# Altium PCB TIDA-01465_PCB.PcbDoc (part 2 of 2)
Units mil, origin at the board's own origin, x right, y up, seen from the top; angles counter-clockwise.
Board outline 2770 x 2010 mil, 4 copper layers (Top Layer, MidLayer1, MidLayer2, Bottom Layer), stack 61.2 mil thick; 110 components, 69 nets, 347 pads, 90 vias.
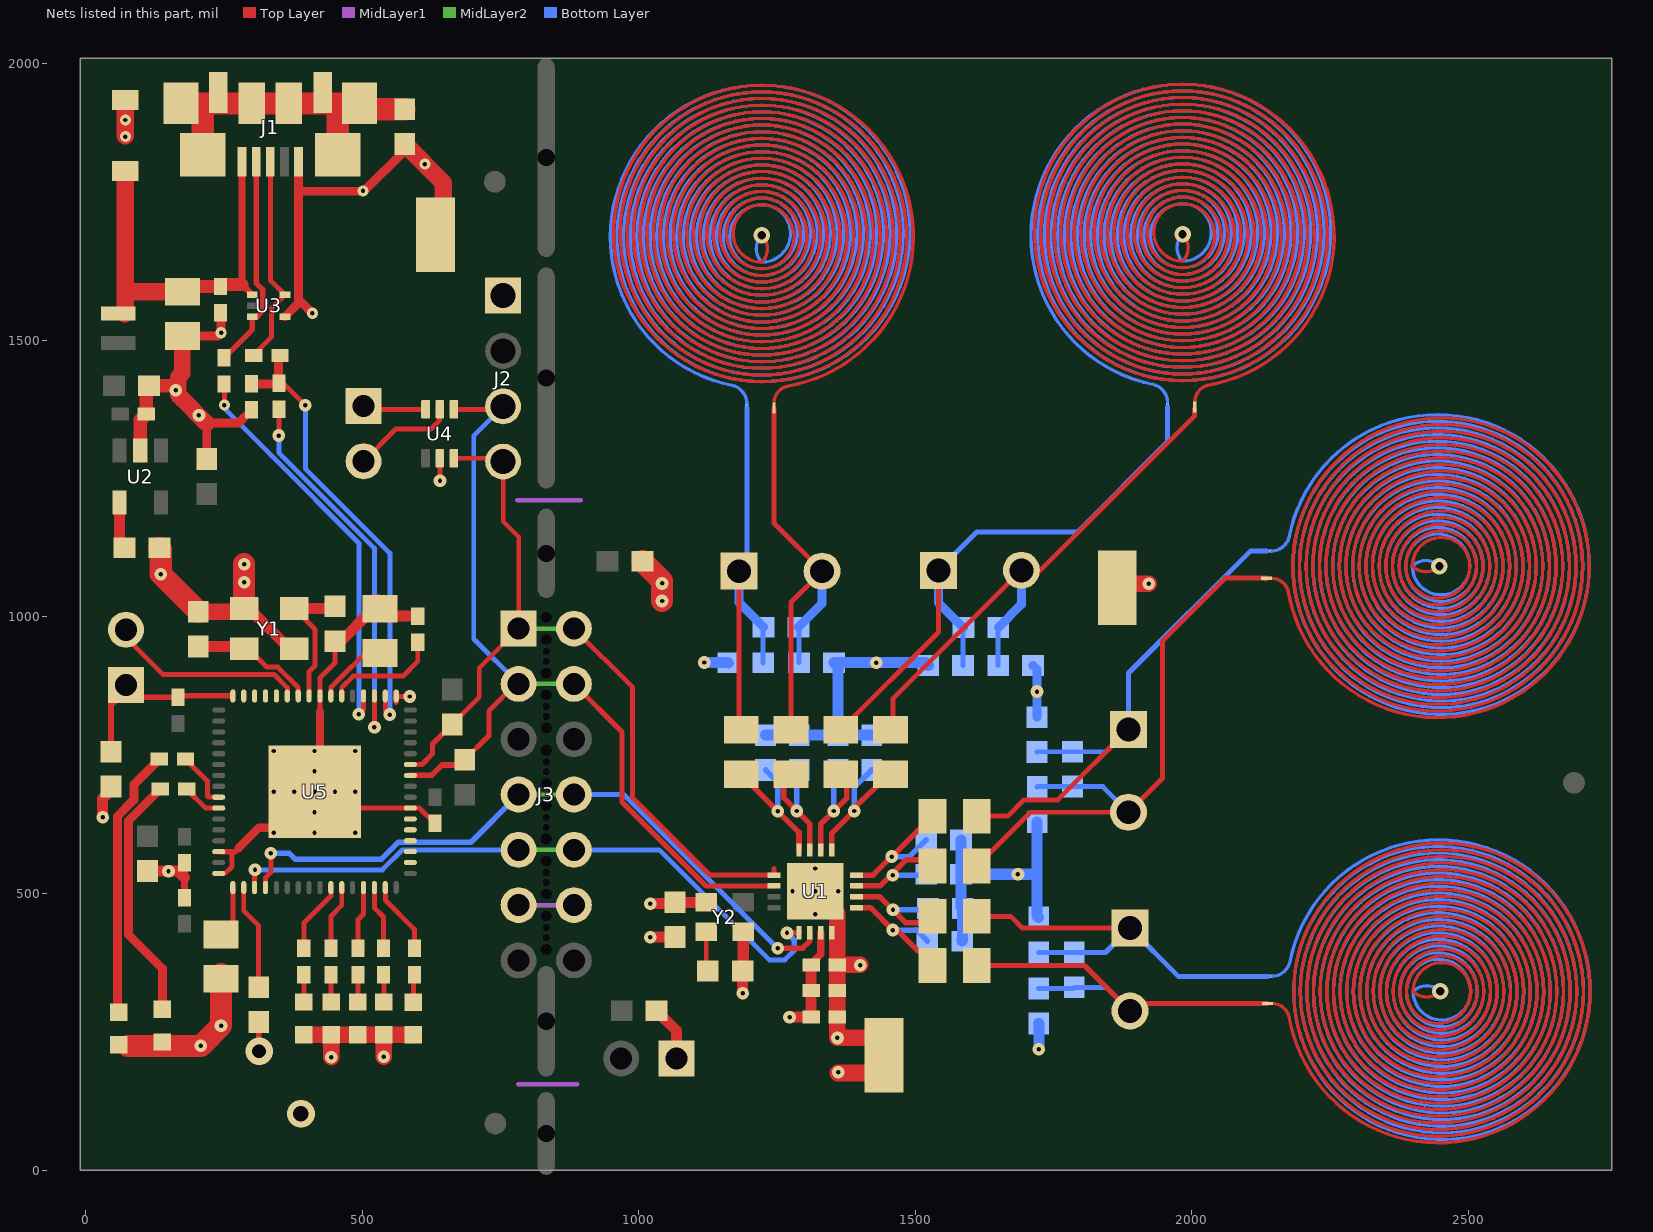
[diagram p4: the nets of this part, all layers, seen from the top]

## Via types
v1: diameter 23, hole 8, Top Layer to Bottom Layer, tented both sides, 58 vias
v2: diameter 19.68, hole 7.87, Top Layer to Bottom Layer, 18 vias
v3: diameter 20, hole 8, Top Layer to Bottom Layer, tented both sides, 7 vias
v4: diameter 30, hole 15, Top Layer to Bottom Layer, tented both sides, 4 vias
v5: diameter 50, hole 25, Top Layer to Bottom Layer, 2 vias
v6: diameter 50, hole 28, Top Layer to Bottom Layer, 1 vias

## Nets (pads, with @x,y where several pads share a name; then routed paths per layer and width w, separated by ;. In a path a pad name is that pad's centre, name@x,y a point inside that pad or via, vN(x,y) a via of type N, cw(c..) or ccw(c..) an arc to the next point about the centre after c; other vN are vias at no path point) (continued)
GND: C1.2 C2.2 C3.2 C4.2 C5.2 C6.2 C8.2 C9.2 C11.1 C12.1 C13.1 C14.1 C16.2 C18.2 C19.1 C20.1 C21.1 C23.2 C25.2 C26.2 C27.1 C28.2 C29.2 C30.2 C31.2 C32.2 C33.2 C34.2 C35.2 C36.2 C37.1 C38.2 C39.1 C41.2 C42.1 C44.2 D1.2 D2.2 D3.2 D4.2 D5.2 D6.2 D7.2 D8.1 GND1.1 GND2.1 GND3.1 J1.5 J2.1 J3.11 J3.12 R7.1 R15.1 R16.1 U1.8 U1.17 U2.2 U3.4 U4.2 U5.14 U5.16 U5.39 U5.49 U5.56 U5.65 Y1.2 Y1.4 Y2.2 | length 6001.8
  Top Layer w9: U5.16@240.77,536.36 241.05,536.64 252.81,536.64 265.08,548.91 265.08,570.23 ; U5.65@331,619 396,684 v2(414,684) ; v2(340.18,684) 354,684 U5.65@420.91,750.91 ; 423.85,829 U5.56@423.85,857.23 423.85,889.99 450.96,917.11 C14.1@450.96,945.31 ; U5.65@443.53,654.47 U5.39@587.23,654.47 603.82,654.47 C33.2@631.54,626.75 ; U5.49@561.67,845.47 U5.49@561.67,857.23 562.71,856.19 v1(586.36,856.19) ; U4.2@640.39,1287.05 640.02,1286.67 640.83,1285.87 v1(640.83,1246.36) ; R16.1@1188.14,359.81 R16.1@1189.18,360.85
  Top Layer w10: U5.14@240.77,575.73 270.59,575.73 276.93,582.07
  Top Layer w12: C32.2@178.89,492.62 C32.2@179,492.62 179,529 C30.2@179,555.38
  Top Layer w15: 276.93,582.07 313.86,619 U5.65@331,619 ; U5.65@423.85,693.84 423.85,829
  Top Layer w16: C31.2@112,535.18 C31.2@112,540.5 ; 175,1394 175,1394.12 ; C8.2@175,1508 239,1508 v3(245,1514) C9.2@245,1549.38 ; 218,1351 276.62,1351 R15.1@300,1374.38 ; C3.2@219,1285.5 219,1350 ; U3.4@360.53,1543.32 385.18,1567.97 ; J1.5@385.18,1823.22 385.18,1769.73 ; v3(410.01,1549.25) 391.29,1567.97 385.18,1567.97 ; R7.1@577,1855.23 577,1843.43 503.29,1769.73 385.18,1769.73 ; 385.18,1567.97 385.18,1769.73
  Top Layer w20: v1(31,638) 31,671.4 30.7,671.7 C27.1@46,687 ; C31.2@112,540.5 167.5,540.5 179,529 ; Y1.2@286.72,1015.42 295.58,1015.42 368.42,942.58 Y1.4@377.28,942.58 ; C14.1@450.96,945.31 528.74,1023.09 C26.2@528.74,1031.81 ; C26.2@541.58,1001.55 C29.2@603.3,1001.55 ; v1(1020.94,421.02) 1065.57,421.02 C5.2@1065.83,421.28 ; R16.1@1188.14,359.81 1188.25,359.71 v1(1188.25,319.59) ; R16.1@1189.18,360.85 Y2.2@1189.18,430.63
  Top Layer w25: U2.2@99,1301.24 99,1356.21 C2.2@109.61,1366.82 109.61,1413.11 C1.2@114.5,1418 151.12,1418
  Top Layer w30: v1@167.38,1410 167.38,1401.74 175,1394.12 ; v1@167.38,1418 167.38,1433.39 175,1441.01 C8.2@175,1508 ; 175,1394 218,1351 219,1350 ; C13.1@204,1009.5 280.8,1009.5 Y1.2@286.72,1015.42 ; D4.2@394.55,244.76 D5.2@444.16,244.76 ; v1(444.16,203.92) D5.2@444.16,244.76 ; v1(539.4,204.69) D7.2@539.4,244.76 ; D8.1@593,243.64 591.87,244.76 D7.2@539.4,244.76 ; v2(1319.55,503.84) 1359.17,464.22 C6.2@1359.17,370.84 ; v1@1360.49,175.4 GND3.1@1444.15,175.4 ; v1@1400.28,370.84 C6.2@1359.17,370.84 ; GND3.1@1443.64,239.27 1443.21,238.84 v1(1359.55,238.84) 1359.17,239.22 C25.2@1359.17,276.84 C34.2@1359.17,324.84 C6.2@1359.17,370.84 ; GND1.1@1865.41,1053.14 1872.45,1060.19 v1(1922.53,1060.19) ; D5.2@444.16,244.76 D6.2@492.53,244.76 D7.2@539.4,244.76
  Top Layer w32: v3@72,1870.74 D1.2@72,1935.2 ; R7.1@577,1855.23 647,1785.23 GND2.1@647,1703.73
  Top Layer w40: 77,224.47 v1(208.47,224.47) v1(245,261) C28.2@245,354.5 ; C4.2@133.5,1125 135.99,1122.5 v1(135.99,1077.5) C13.1@204,1009.5 ; Y1.2@286.72,1015.42 v1(286.72,1095.28)
  MidLayer1 w8: 780.45,1210.95 895.45,1210.95 ; 782,155 889,155 ; J3.11@793,479 J3.12@883,479 J3.12@893,479
  MidLayer2 w8: J3.11@773,479 J3.11@783,479 J3.12@883,479
  Bottom Layer w16: C36.2@1713.19,912.33 1720.36,905.16 C42.1@1720.36,818.85
  Bottom Layer w20: v1(1118.75,917.78) 1161.66,917.78 C12.1@1162.25,917.19 ; C11.1@1229.55,786.34 C16.2@1290.55,786.34 C19.1@1360.55,786.34 ; C35.2@1421.55,786.34 C19.1@1360.55,786.34 ; C21.1@1523.72,912.33 1518.55,917.5 C18.2@1353.08,917.53 1360.55,910.07 C19.1@1360.55,786.34 ; C20.1@1583.04,596.84 C23.2@1583.04,534.84 ; C38.2@1585.04,413.84 1586.04,414.84 C37.1@1586.04,472.84 1583.04,475.84 C23.2@1583.04,534.84 ; 1720.17,534.84 C23.2@1583.04,534.84 ; C44.2@1720.61,629.39 1720.61,459.14 C39.1@1723.36,456.4 ; C41.2@1723.36,265.2 1723.7,264.85 v1(1723.7,218.41)
  other v1: 1360.99,176.57 1400.93,370.19 1685.9,534.76 150,540.5 1720.45,865.18 1429.67,917.4 286.72,1063 205,1365 163,1410
  other v2: 1319.55,462.5 1278.21,503.84 1360.89,503.84 1319.55,545.18 340.18,610.18 414,610.18 487.82,610.18 414,647.09 377.09,684 450.91,684 487.82,684 414,720.91 340.18,757.82 414,757.82 487.82,757.82
  other v3: 501.61,1770.4 613.5,1818.73 72,1868.73 72,1898.73
  other v6: 389.44,101.69
IN0A: C38.1 R33.1 U1.9 | length 226.6
  Top Layer w10: U1.9@1389.35,474.31 1419.07,474.31 v1(1459.55,433.84) 1467.55,433.84 1504.43,396.96 ; R33.1@1523.55,369.84 R33.1@1531.55,369.84
  Bottom Layer w10: v1(1459.55,433.84) 1500.41,433.84 1501.23,434.66 C38.1@1522.05,413.84
IN0B: C37.2 R23.1 U1.10 | length 209.8
  Top Layer w10: U1.10@1389.35,494 1436.39,494 v1(1459.97,470.42) 1483.55,446.84 R23.1@1515.55,446.84
  Bottom Layer w10: v1(1459.97,470.42) 1520.63,470.42 C37.2@1523.05,472.84
IN1A: C23.1 R20.1 U1.11 | length 205.1
  Top Layer w10: U1.11@1389.35,513.68 1436.39,513.68 1483.55,560.84 R20.1@1513.55,560.84
  Bottom Layer w10: v1(1459.55,532.84) 1518.05,532.84 C23.1@1520.05,534.84
IN1B: C20.2 R19.1 U1.12 | length 261.2
  Top Layer w10: U1.12@1389.35,533.37 1409.16,533.37 1424.07,533.37 v1(1457.55,566.84) 1458.55,566.84 R19.1@1531.55,639.84
  Bottom Layer w10: v1(1457.55,566.84) 1490.05,566.84 C20.2@1520.05,596.84
IN2A: C35.1 R28.1 U1.13 | length 269.3
  Top Layer w10: U1.13@1349.07,578.64 1349.07,608.6 v1(1389.74,649.26) 1389.74,654.97 1450.48,712.68 1455.46,712.56 R28.1@1455.55,712.55
  Bottom Layer w10: v1(1389.74,649.26) 1389.74,691.54 C35.1@1421.55,723.34
IN2B: C19.2 R27.1 U1.14 | length 223
  Top Layer w10: U1.14@1329.39,578.64 1329.39,625.68 v1(1352.97,649.26) 1376.55,672.84 R27.1@1376.55,704.84
  Bottom Layer w10: v1(1352.97,649.26) 1352.97,715.77 C19.2@1360.55,723.34
IN3A: C16.1 R26.1 U1.15 | length 219.6
  Top Layer w10: R26.1@1262.55,702.84 1262.55,672.84 1309.7,625.68 U1.15@1309.7,578.64
  Bottom Layer w10: v1(1286.13,649.26) 1286.13,718.92 C16.1@1290.55,723.34
IN3B: C11.2 R24.1 U1.16 | length 264.1
  Top Layer w10: R24.1@1185.55,715.84 1185.55,714.84 v1(1251.55,648.84) 1290.02,610.37 U1.16@1290.02,578.64
  Bottom Layer w10: C11.2@1229.55,723.34 1251.55,701.34 v1(1251.55,648.84)
INTB: J3.9 J3.10 U1.5 U5.19 | length 1154.1
  Top Layer w9: U5.19@305.71,510.77 v1@305.71,542.13
  Top Layer w10: v1@1273.13,429.04 U1.5@1290.02,429.04
  MidLayer2 w8: J3.9@783,579 J3.10@873,579
  Bottom Layer w9: v1(306.32,542.75) 536.73,542.75 572.98,579 ; 573.95,579 J3.9@783,579 ; J3.10@883,579 1037.28,579 1236.29,379.98 1264.39,379.98 1281.45,397.05
  Bottom Layer w10: v1(1268.3,428.77) 1281.45,415.62 1281.45,397.05
JTAG_RST: C27.2 J9.1 R29.2 U5.64 | length 404.6
  Top Layer w10: C27.2@46,756.5 46,840 ; U5.64@266.33,857.23 164.39,857.23 R29.2@167,854.62 J9.1@95.38,854.62 ; 46,840 71,865 81.38,854.62 J9.1@95.38,854.62 ; 46,840 46,850 J9.1@73,877 J9.1@95.38,854.62
JTAG_TCK: U5.63
JTAG_TDI: U5.61
JTAG_TDO: U5.60
JTAG_TEST: J9.2 U5.59 | length 352.9
  Top Layer w9: J9.2@67,969 139.66,896.34 340.75,896.34 364.78,872.32 U5.59@364.78,857.23
JTAG_TMS: U5.62
MSP_DM: R9.2 U5.52 | length 735.7
  Top Layer w9: R9.2@249.62,1421 R9.2@250,1421.38 250.84,1420.54 v3(250.84,1383.04) ; v1(494.07,824.02) 502.61,832.55 U5.52@502.61,857.23
  Bottom Layer w9: v3(250.84,1383.04) 250.84,1377.16 336.46,1291.54 336.46,1291.39 494.07,1133.78 v1(494.07,824.02)
MSP_DP: R6.1 R8.2 R15.2 U5.50 | length 821.2
  Top Layer w9: R6.1@350,1422.62 357.71,1422.62 v1(397.42,1382.92) ; U5.50@541.98,857.23 541.98,831.75 v1(550.14,823.6)
  Top Layer w16: R15.2@300,1421.62 349,1421.62 R8.2@349,1470.38
  Bottom Layer w9: v1(397.42,1382.92) 397.42,1268.27 550.14,1115.54 v1(550.14,823.6)
MSP_PUR: R6.2 U5.51 | length 702.8
  Top Layer w9: v1@350,1328.58 R6.2@350,1375.38 ; v1(522.3,800.45) U5.51@522.3,857.23
  Bottom Layer w9: v1(349.46,1328.05) 349.46,1297.17 522.3,1124.34 v1(522.3,800.45)
MSPACLK: R17.2 | length 53.1
  Top Layer w10: R17.2@313,267.5 313,230 313.87,229.13 v5(313.87,214.74)
NetC4_1: C4.1 U2.4 | length 85.4
  Top Layer w20: U2.4@61.6,1206.76 61.6,1133.91 C4.1@70.5,1125
NetC7_1: C7.1 C18.1 J7.2 L3.1 R26.2 | length 825
  Top Layer w9: L3.1@1244.67,1377.96 1244.67,1169.91 J7.2@1331.83,1082.75 1275.55,1026.46 R26.2@1275.55,795.84
  Bottom Layer w9: C7.1@1288.98,981.73 1290.09,980.62 C18.1@1290.09,917.53
  Bottom Layer w16: C7.1@1288.98,981.73 1331.83,1024.58 J7.2@1331.83,1082.75
NetC7_2: C7.2 C12.2 J7.1 L3.2 R24.2 | length 780.2
  Top Layer w9: R24.2@1181.83,799.55 J7.1@1181.83,1082.75
  Top Layer w16: R24.2@1181.83,799.55 R24.2@1185.55,795.84
  Bottom Layer w9: J7.1@1181.83,1082.75 J7.1@1181.83,1108.81 ; J7.1@1195.61,1096.52 1195.61,1122.58 L3.2@1195.61,1378.04 ; C12.2@1225.24,917.19 1225.24,980.98 C7.2@1225.99,981.73
  Bottom Layer w16: J7.1@1181.83,1082.75 1181.83,1025.89 C7.2@1225.99,981.73
  other v4: 1222.84,1690.53
NetC10_1: C10.1 C36.1 J6.2 L2.1 R28.2 | length 1017.5
  Top Layer w9: R28.2@1455.55,795.84 1459.79,800.08 1459.79,852.07 J6.2@1692.14,1084.42 1726.24,1084.42 2005.47,1363.64 L2.1@2005.47,1376.15
  Bottom Layer w9: C36.1@1650.2,912.33 1650.2,980.82 C10.1@1650.3,980.91
  Bottom Layer w16: C10.1@1650.3,980.91 1692.14,1022.76 J6.2@1692.14,1084.42
NetC10_2: C10.2 C21.2 J6.1 L2.2 R27.2 | length 1126.6
  Top Layer w9: R27.2@1365.55,795.84 1542.14,972.44 J6.1@1542.14,1084.42
  Bottom Layer w9: J6.1@1542.14,1084.42 1611.5,1153.78 1793.85,1153.78 1956.4,1316.34 L2.2@1956.4,1379.85 ; C21.2@1586.71,912.33 1586.71,980.31 C10.2@1587.3,980.91
  Bottom Layer w16: J6.1@1542.14,1084.42 1542.14,1026.07 C10.2@1587.3,980.91
  other v4: 1983.64,1692.34
NetC13_2: C13.2 U5.58 Y1.3 | length 226.3
  Top Layer w9: Y1.3@286.72,942.58 294.78,942.58 328.02,909.34 347.55,909.34 384.46,872.43 U5.58@384.46,857.23
  Top Layer w20: C13.2@204,946.5 282.8,946.5 Y1.3@286.72,942.58
NetC14_2: C14.2 U5.57 Y1.1 | length 260.1
  Top Layer w9: Y1.1@377.28,1015.42 415.25,977.44 415.25,912.2 404.15,901.1 U5.57@404.15,857.23
  Top Layer w20: Y1.1@377.28,1015.42 455.92,1015.42 C14.2@458,1017.5
NetC15_1: C15.1 C44.1 J5.2 L1.1 R20.2 | length 1068.6
  Top Layer w9: R20.2@1611.55,549.84 1708.67,646.96 J5.2@1885.73,646.96 1947.62,708.85 1947.62,957.16 2060.58,1070.13 L1.1@2131.91,1070.13 ; L1.1@2133.72,1068.32 L1.1@2135.53,1070.13
  Bottom Layer w9: C44.1@1720.61,692.38 1721.58,693.34 C15.1@1784.46,693.34 1839.34,693.34 J5.2@1885.73,646.96
NetC15_2: C15.2 C42.2 J5.1 L1.2 R19.2 | length 964.6
  Top Layer w9: R19.2@1611.55,639.84 1667.43,639.84 1696.92,669.34 1758.11,669.34 J5.1@1885.73,796.96
  Bottom Layer w9: C42.2@1720.36,755.86 1720.84,756.34 C15.2@1784.46,756.34 1845.11,756.34 J5.1@1885.73,796.96 1885.73,898.78 2106.14,1119.19 L1.2@2135.61,1119.19
  other v4: 2448.1,1091.96
NetC17_1: C17.1 C41.1 J4.2 L0.1 R33.2 | length 748.9
  Top Layer w9: R33.2@1611.55,369.84 1806.3,369.84 J4.2@1888.57,287.57 1902.27,301.27 L0.1@2136.87,301.27
  Bottom Layer w9: C41.1@1723.36,328.19 1785.83,328.19 C17.1@1788,330.36 1845.78,330.36 J4.2@1888.57,287.57
NetC17_2: C17.2 C39.2 J4.1 L0.2 R23.2 | length 753.9
  Top Layer w9: R23.2@1611.55,458.84 1672.68,458.84 1693.95,437.57 J4.1@1888.57,437.57
  Bottom Layer w9: C39.2@1723.36,393.41 1787.94,393.41 C17.2@1788,393.35 1844.35,393.35 J4.1@1888.57,437.57 1975.8,350.33 L0.2@2136.94,350.33
  other v4: 2449.43,323.1
NetC26_1: C26.1 U5.55 | length 137.6
  Top Layer w9: U5.55@443.54,857.23 443.54,872.43 522.97,951.87 C26.1@533.04,951.87
NetC28_1: C28.1 U5.17 | length 102.3
  Top Layer w9: C28.1@245,417.5 266.5,439 266.5,510.6 U5.17@266.33,510.77
NetD2_1: D2.1 R21.2 | length 489.8
  Top Layer w16: D2.1@60,285.53 57.65,287.88 57.65,639.56 87.4,669.31 87.4,697.03 R21.2@133.38,743
NetD3_1: D3.1 R25.2 | length 447.8
  Top Layer w16: R25.2@135.38,689 77.65,631.27 77.65,425.75 139,364.41 D3.1@139,290.53
NetD4_1: D4.1 R1.1 | length 49.6
  Top Layer w9: D4.1@394.55,303.81 R1.1@394.55,353.43
NetD5_1: D5.1 R2.1 | length 49.6
  Top Layer w9: D5.1@444.16,303.81 R2.1@444.16,353.43
NetD6_1: D6.1 R3.1 | length 49.6
  Top Layer w9: D6.1@492.53,303.81 R3.1@492.53,353.43
NetD7_1: D7.1 R4.1 | length 49.8
  Top Layer w9: R4.1@538.87,353.43 539.4,352.9 D7.1@539.4,303.81
NetD8_2: D8.2 R5.1 | length 51.4
  Top Layer w9: D8.2@593,302.69 593,351.87 R5.1@594.56,353.43
NetJ1_2: J1.2 R9.1 U3.3 | length 393.8
  Top Layer w10: R9.1@250,1468.62 301.47,1520.09 U3.3@301.47,1543.32 310.26,1543.32 320.31,1553.37 320.31,1592.32 308.41,1604.22 J1.2@308.41,1823.22
NetJ1_3: J1.3 R8.1 U3.5 | length 384.5
  Top Layer w9: R8.1@304.38,1473 304.38,1474.47 335.98,1506.08 335.98,1558.14 U3.5@360.53,1582.69 334,1609.21 J1.3@334,1823.22
NetJ1_6: J1.6 J1.7 J1.8 J1.9 J1.10 J1.11 J1.12 J1.13 R7.2 | length 725
  Top Layer w40: J1.13@178,1928.73 J1.8@495.42,1928.73 ; J1.7@211.95,1836.21 211.95,1927.68 ; 211.95,1928.73 J1.11@300.54,1928.73 J1.10@367.46,1928.73 ; J1.6@456.05,1836.21 456.05,1925.68 ; J1.8@505.92,1918.22 R7.2@577,1918.22
NetJ10_1: J10.1 U4.6 | length 106.1
  Top Layer w9: J10.1@508.66,1375.63 U4.6@614.8,1375.63
NetJ10_2: J10.2 U4.5 | length 188.3
  Top Layer w9: J10.2@502.74,1281.55 561.08,1339.89 624.55,1339.89 640.39,1355.74 U4.5@640.39,1375.63
NetR1_2: R1.2 U5.26 | length 130.4
  Top Layer w9: R1.2@394.55,400.68 394.55,446.59 443.54,495.57 U5.26@443.54,510.77
NetR2_2: R2.2 U5.27 | length 118
  Top Layer w9: R2.2@444.16,400.68 444.16,459.48 463.22,478.54 U5.27@463.22,510.77
NetR3_2: R3.2 U5.29 | length 114.3
  Top Layer w9: R3.2@492.53,400.68 492.53,452.84 502.61,462.92 U5.29@502.61,510.77
NetR4_2: R4.2 U5.30 | length 117
  Top Layer w9: U5.30@522.3,510.77 522.3,474.12 538.87,457.54 R4.2@538.87,400.68
NetR5_2: R5.2 U5.31 | length 131.9
  Top Layer w9: U5.31@541.98,510.77 541.98,488.17 594.56,435.6 R5.2@594.56,400.68
NetR16_2: R16.2 Y2.1 | length 72
  Top Layer w8: Y2.1@1122.25,430.63 1122.25,362.72 R16.2@1125.15,359.81
NetR17_1: R17.1 U5.18 | length 191.5
  Top Layer w9: U5.18@286.01,510.77 286.01,468.64 313,441.66 R17.1@313,330.5
NetR21_1: R21.1 U5.9 | length 104.7
  Top Layer w9: R21.1@180.62,743 220.46,703.16 220.46,675.85 222.16,674.16 U5.9@240.77,674.16
NetR25_1: R25.1 U5.10 | length 72.5
  Top Layer w9: R25.1@182.62,689 217.15,654.47 U5.10@240.77,654.47
P3.0: U5.34
P3.1: U5.35
P3.2: U5.36
P3.3: U5.37
P3.4: U5.38
SCL: J2.4 J3.1 J3.2 R13.2 U1.1 U4.3 U5.43 | length 1511.5
  Top Layer w8: R13.2@662.89,805.82 711.89,854.83 711.89,907.89 J3.1@783,979 783,1144.93 755,1172.93 J2.4@755,1281 ; U4.3@665.98,1287.05 J2.4@748.95,1287.05
  Top Layer w9: U5.43@587.23,733.21 608.21,733.21 627.47,752.47 627.47,770.41 R13.2@662.89,805.82 ; J3.2@883,979 989.13,872.87 989.13,672.87 1128.63,533.37 U1.1@1244.74,533.37 1244.74,545.64
  MidLayer2 w8: J3.1@783,979 J3.2@883,979
SD: J3.7 J3.8 U1.6 U5.20 | length 1218.9
  Top Layer w9: U5.20@325.39,510.77 325.39,528.74 335.01,538.35 v1(335.01,572.72)
  Top Layer w10: v1(1251.54,401.23) 1296.71,401.23 1309.7,414.23 U1.6@1309.7,429.04
  MidLayer2 w8: J3.7@783,679 J3.8@873,679
  Bottom Layer w9: J3.8@883,679 972.99,679 v1@1251.15,400.84
  Bottom Layer w10: v1(335.01,572.72) 368.39,572.72 379.56,561.55 534.29,561.55 565.24,592.5 696.5,592.5 J3.7@783,679
SDA: J2.3 J3.3 J3.4 R12.2 U1.2 U4.4 U5.42 | length 1618.8
  Top Layer w9: U4.4@665.98,1375.63 J2.3@749.63,1375.63 ; R12.2@685.49,741.76 729.5,785.77 729.5,830.5 778,879 J3.3@783,879 ; J3.4@883,879 970.03,791.97 970.03,665.61 1121.96,513.68 U1.2@1244.74,513.68
  Top Layer w10: U5.42@587.23,713.53 625.75,713.53 644.63,732.41 676.14,732.41 R12.2@685.49,741.76
  MidLayer2 w8: J3.3@783,879 J3.4@883,879
  Bottom Layer w9: J2.3@755,1381 701.93,1327.93 701.93,960.07 J3.3@783,879
VBUS: C8.1 C9.1 D1.1 J1.1 L10.1 U3.1 | length 719.6
  Top Layer w12: J1.1@282.82,1823.22 282.82,1601.34 U3.1@301.47,1582.69
  Top Layer w24: C8.1@175,1588 184.62,1597.62 C9.1@244,1597.62 ; C9.1@247.72,1601.34 282.82,1601.34
  Top Layer w32: L10.1@71,1548.57 72,1549.57 72,1593.32 ; D1.1@72,1806.26 72,1593.32 ; C8.1@175,1588 77.32,1588 72,1593.32
VDD: C5.1 C6.1 C25.1 C34.1 J8.1 R10.2 R18.2 U1.7 Y2.4 | length 487
  Top Layer w14: C6.1@1311.92,372.84 1329.39,390.3 U1.7@1329.39,429.04
  Top Layer w20: v1(1020.94,481.59) 1063.14,481.59 C5.1@1065.83,484.27 1066.32,483.78 Y2.4@1122.25,483.78 ; R10.2@1032.37,287.98 1068.5,251.86 J8.1@1068.5,201.68 ; v1(1273.05,276.48) 1311.57,276.48 C25.1@1311.92,276.84 C34.1@1311.92,324.84 C6.1@1311.92,370.84
  Top Layer w40: R18.2@1006.9,1100.89 1042.41,1065.39 v1(1042.41,1028.89)
  other v1: 1042.41,1060.66
VUSB: C29.1 U5.54 | length 206.6
  Top Layer w9: U5.54@463.22,857.23 463.22,872.43 483.78,892.98 573.85,892.98 600.64,919.77 C29.1@600.64,954.13
pads on no net: FID1.1 FID2.1 FID3.1 J1.4 U3.2 U5.1 U5.2 U5.3 U5.4 U5.5 U5.6 U5.7 U5.8 U5.12 U5.13 U5.22 U5.23 U5.24 U5.25 U5.28 U5.32 U5.33 U5.41 U5.44 U5.45 U5.46 U5.47 U5.48

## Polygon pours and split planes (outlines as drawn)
GND on MidLayer1 "Bottom Layer-No Net" (solid, pour order 17): 20,20 793,20 793,1966.1 20,1966.1
GND on MidLayer1 "Bottom Layer-No Net" (solid, remove dead copper, pour order 20): 875,35 1984.48,35 1984.48,1230.07 875,1230.07
+3.3V on MidLayer2 "Bottom Layer-No Net" (solid, pour order 14): 20,770 790,770 790,1840 20,1840
+3.3V on MidLayer2 "Bottom Layer-No Net" (solid, pour order 16): 17,17 791,17 791,770.5 17,770.5 17,17
+3.3V on MidLayer2 "Bottom Layer-No Net" (solid, remove dead copper, pour order 19): 875,35 1983.8,35 1983.8,1232.3 875,1232.3
VDD on MidLayer2 "Bottom Layer-No Net" (solid, remove dead copper, pour order 18): 1001.04,204.41 1628.76,204.41 1628.76,1232.3 1001.04,1232.3

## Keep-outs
Keep-Out Layer:
  lines w8: 2758.77,0.52 -10,-0.01 -10,2010 2760,2010 2760.04,0
  text ".Layer_Name" at 577,-858.49 h60

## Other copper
Top Layer:
  text ".Layer_Name" at 577,-858.49 h60
MidLayer1:
  pour cut-out: 154.5,894 154.7,894.2 154.7,1052.87 485.63,1052.87 497.5,1040.99 497.5,888
MidLayer2:
  pour cut-out: 154.5,894 154.7,894.2 154.7,1052.87 485.63,1052.87 497.5,1040.99 497.5,888
Bottom Layer:
  text ".Layer_Name" at 577,-858.49 h60

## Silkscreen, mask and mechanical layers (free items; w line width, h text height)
Top Overlay:
  text "GND" at 574.05,1648.35 h30 r90
  text "TIDA-01465" at 1324.49,1421.13 h60
  text "CH3" at 1180.92,1249.67 h55
  text "CH2" at 1527.35,1246.96 h60
  text "+5V" at 417,1165 h30
  text "GND" at 1960.94,1010.82 h30 r90
  text "SBW" at 161,898 h25 r90
  text "CH1" at 2110.61,631.22 h60 r90
  text "FDC" at 1278.02,597.54 h40
  text "or" at 1020.34,495.84 h30 r90
  text "CH0" at 2112.07,289.81 h60 r90
  text "+3.3V" at 942.02,113.51 h30
  text "GND" at 437.22,84.68 h30
  text "ACLK" at 320.13,73.04 h30 r90
  text ".Layer_Name" at 577,-858.49 h60
  text "CH0" at 2292,-1832 h60
Bottom Overlay:
  text "0.15mm trace width" at 2630,1804 h40 r90
  text "0.15mm trace spacing" at 2688,1804 h40 r90
  text "19 turns/layer" at 2514,1803 h40 r90
  text "2 layers" at 2572,1803 h40 r90
  text "SENSOR: 13.9mm" at 2456,1802 h40 r90
  text "TCK" at 100,1042 h25
  text "SCL" at 1015,968 h30
  text "SDA" at 1015,865 h30
  text "TDIO" at 113,791 h25
  text "ADDR" at 1044.99,762 h30
  text "SD" at 985.01,660.65 h30
  text "INTB" at 1039.99,565 h30
  text "GND" at 1015,469.61 h30
  text "3.3V" at 1039.99,363 h30
  text ".Layer_Name" at 577,-858.49 h60
Top Paste:
  text ".Layer_Name" at 577,-858.49 h60
Bottom Paste:
  text ".Layer_Name" at 577,-858.49 h60
Top Solder:
  text ".Layer_Name" at 577,-858.49 h60
  text ".Layer_Name" at 577,-858.49 h60
Bottom Solder:
  text ".Layer_Name" at 577,-858.49 h60
Drill Guide:
  text ".Layer_Name" at 577,-858.49 h60
M1 Board Outline:
  the board outline again, w8
  text ".Layer_Name" at 577,-858.49 h60
M2 Board Dimensions:
  rectangle: 124.5,-410.5 499.5,-285.5
  rectangle: -0.5,-285.5 124.5,-160.5
  lines w7: -0.5,-285.5 999.5,-285.5 ; 124.5,-410.5 124.5,-160.5 ; 249.5,-410.5 249.5,-160.5 ; 499.5,-410.5 499.5,-160.5 ; 749.5,-410.5 749.5,-160.5 ; -0.5,-410.5 -0.5,-160.5 999.5,-160.5 999.5,-410.5 -0.5,-410.5
  lines w10: -0.5,-475.5 -0.5,-455.5 ; 59.5,-485.5 -0.5,-465.5 ; 59.5,-445.5 -0.5,-465.5 ; 223.58,-465.5 -0.5,-465.5 ; 775.42,-465.5 999.5,-465.5 ; 939.5,-485.5 999.5,-465.5 ; 939.5,-445.5 999.5,-465.5 ; 999.5,-475.5 999.5,-455.5
  text "1000 (mil)" at 233.58,-501.49 h60
  text ".Layer_Name" at 577,-858.49 h60
M3 3D STEP Top:
  text ".Layer_Name" at 577,-858.49 h60
M4 3D STEP Bottom:
  text ".Layer_Name" at 577,-858.49 h60
M5 Assembly Top:
  lines w10: -292,-930.17 6308,-930.17 ; -292,-726.83 6310,-726.83 ; -292,-523.5 -292,-1133.5 3713,-1133.5 6310,-1133.5 6310,-523.5 -291.5,-523.5 -291.5,-1133.5 1284,-1133.5 ; 2173,-1133.5 2173,-523.5 ; 3440,-726.83 3440,-523.5 ; 4280,-726.83 4280,-523.5 ; 4902,-1140 4902,-937.17
  text "COMPONENTS MARKED 'DNP' SHOULD NOT BE POPULATED." at 1153.5,-318.5 h60
  text "ASSEMBLY VARIANT:" at 1153,-434 h60
  text ".VariantName" at 2189,-434 h60
  text "PCB VIEWED FROM TOP SIDE" at -228.5,-655.67 h60
  text "BOARD #:" at 2248,-655.67 h60
  text ".PRJ_Number" at 2793.5,-655.67 h60
  text "REV:" at 3638,-655.67 h60
  text ".PCB_Rev" at 3929.5,-655.67 h60
  text "SVN REV:" at 4476,-655.67 h60
  text ".VersionControl_RevNumber" at 4982,-655.67 h60
  text "IGNORE ->" at -228.5,-858.49 h60
  text "PLOT NAME =" at -228.5,-1064.34 h60
  text ".plot_File_Name" at 577,-1064.34 h60
  text "GENERATED    :" at 2250,-1064.34 h60
  text ".Print_Date" at 3119.5,-1064.34 h60
  text ".Print_Time" at 3848.5,-1064.34 h60
  text "TEXAS INSTRUMENTS" at 5113,-1064.34 h60
M6 Assembly Bottom:
  lines w10: -292.5,-727.33 6309.5,-727.33 ; -290.5,-930.67 6309.5,-930.67 ; 1115.5,-1140.5 1115.5,-937.67 ; 1737.5,-727.33 1737.5,-524 ; 2577.5,-727.33 2577.5,-524 ; 3844.5,-1134 3844.5,-524 ; 4733.5,-1134 6309,-1134 6309,-524 -292.5,-524 -292.5,-1134 2304.5,-1134 6309.5,-1134 6309.5,-524
  text "COMPONENTS MARKED 'DNP' SHOULD NOT BE POPULATED." at 6102,-318 h60
  text ".VariantName" at 5058,-434 h60
  text "ASSEMBLY VARIANT:" at 6097,-434 h60
  text ".VersionControl_RevNumber" at 1035.5,-656.17 h60
  text "SVN REV:" at 1541.5,-656.17 h60
  text ".PCB_Rev" at 2088,-656.17 h60
  text "REV:" at 2379.5,-656.17 h60
  text ".PRJ_Number" at 3224,-656.17 h60
  text "BOARD #:" at 3769.5,-656.17 h60
  text "PCB VIEWED FROM BOTTOM SIDE" at 6246,-656.17 h60
  text "IGNORE ->" at 2547.85,-858.49 h60
  text "TEXAS INSTRUMENTS" at 904.5,-1064.84 h60
  text ".Print_Time" at 2169,-1064.84 h60
  text ".Print_Date" at 2898,-1064.84 h60
  text "GENERATED    :" at 3767.5,-1064.84 h60
  text ".plot_File_Name" at 5440.5,-1064.84 h60
  text "PLOT NAME =" at 6246,-1064.84 h60
M9 Title Sheet:
  drawing of 54 lines, arcs and shapes, not listed
  text "1" at 739.84,8036.5 h70
  text "2" at 3235.5,8036.5 h70
  text "3" at 5724.84,8036.5 h70
  text "4" at 8231.51,8036.5 h70
  text "5" at 10730.5,8036.5 h70
  text "6" at 13235.5,8036.5 h70
  text "A" at -416.5,6893.5 h70
  text "A" at 14383.5,6893.5 h70
  text "B" at -416.5,4513.5 h70
  text "B" at 14383.5,4513.5 h70
  text "C" at -416.5,2138.5 h70
  text "C" at 14383.5,2138.5 h70
  text "PROJECT TITLE:" at 11343.5,277.5 h45
  text "Frost and Ice detection" at 11393.5,144.17 h70
  text "DESIGNED FOR:" at 11343.5,-23.5 h45
  text ".PRJ_Customer" at 11393.5,-163.5 h70
  text "D" at -416.5,-231.5 h70
  text "D" at 14383.5,-231.5 h70
  text "FILE NAME:" at 11343.5,-323.5 h45
  text "TIDA-01465_PCB.PcbDoc" at 11393.5,-443.5 h70
  text "Texas Instruments (TI) and/or its licensors do not warrant the accuracy or completeness of this specification" at 6374,-605.34 h45
  text "ENGINEER:" at 11343.5,-613.5 h45
  text "LAYOUT BY:" at 12848.5,-613.5 h45
  text "or any information contained therein. TI and/or its licensors do not warrant that this design will meet" at 6329.01,-718 h45
  text "Richard Wang" at 11393.5,-768.49 h70
  text "Richard Wang" at 12899,-768.49 h70
  text "the specifications, will be suitable for your application or fit for any particular purpose, or will operate in" at 6329.01,-830.67 h45
  text ".Layer_Name" at 577,-858.49 h60
  text "ALTIUM DESIGNER VERSION:" at 12848.5,-923.5 h45
  text "an implementation. TI and/or its licensors do not warrant that the design is production worthy. You should" at 6329.01,-943.33 h45
  text "completely validate and test your design implementation to confirm the system functionality for your application." at 6374,-1056 h45
  text ".print_Scale" at 11393.5,-1056.83 h70
  text ".Application_BuildNumber" at 12899,-1056.83 h70
  text "1" at 739.84,-1263.5 h70
  text "2" at 3235.5,-1263.5 h70
  text "3" at 5724.84,-1263.5 h70
  text "4" at 8231.51,-1263.5 h70
  text "5" at 10730.5,-1263.5 h70
  text "6" at 13235.5,-1263.5 h70
M10 Fab Notes:
  drawing of 212 lines, arcs and shapes, not listed
  text "DESIGN INFORMATION" at 12381.02,6810 h60
  text "(REFER ALSO ARRAY/PANEL PROFILING INFORMATION)" at 12019.46,6648.29 h60
  text "BOARD SIZE" at 11333.46,6644 h60
  text "2760MIL" at 11795.78,6516.18 h60
  text "X" at 12301.46,6516.18 h60
  text "1865MIL" at 12532.78,6516.18 h60
  text "Number of Layers :" at 11736.46,6319 h60
  text "4" at 12831.27,6309 h60
  text "MIN. TRACK WIDTH:" at 11736.46,6180 h60
  text "4" at 12832.7,6180 h60
  text "MIL" at 12987.46,6180 h60
  text "MIN. CLEARANCE:" at 11736.46,6048 h60
  text "4" at 12832.7,6048 h60
  text "MIL" at 12987.46,6048 h60
  text "MIN. VIA PAD SIZE:" at 11736.46,5916 h60
  text "20" at 12802.71,5916 h60
  text "MIL" at 12987.46,5916 h60
  text "0.05mm (2MIL)" at 12431.46,5774.29 h60
  text "MINIMUM ANNULAR RING" at 11407.23,5770 h60
  text "EXTERNAL" at 13139.46,5770 h60
  text "PER" at 11607.23,5652 h60
  text "IPC-D-275 CLASS 2 LEVEL C" at 11827.23,5652 h60
  text "MIL, HOLES" at 13315.46,5539.71 h60
  text "+/-" at 12923,5539 h60
  text "+/-" at 13777,5539 h60
  text "REGISTRATION TOLERANCES:" at 11407.23,5534 h60
  text "METAL" at 12607,5534 h60
  text "5" at 13183.2,5534 h60
  text "3" at 14016.2,5534 h60
  text "MIL" at 14132.46,5534 h60
  text "MATERIAL:" at 11332.46,5324.54 h60
  text "FR-4 High Tg" at 12318.9,5184.21 h60
  text "FR-408" at 11753.46,5175.64 h60
  text "X" at 12165.46,5175.64 h60
  text "OTHER" at 13241.46,5175.64 h60
  text "62 MIL (1.6mm) +/-10%" at 12073.56,5012.92 h60
  text "THICKNESS:" at 11407.23,5008.64 h60
  text "X" at 11945.4,5008.64 h60
  text "OTHER" at 13358.46,5008.64 h60
  text "TOLERANCE:" at 11407.23,4850.64 h60
  text "X" at 12246.53,4850.64 h60
  text "ANSI IPC-6012 TYPE 3 CLASS 2" at 12433.48,4850.64 h60
  text "OTHER +/-" at 12433.46,4694.64 h60
  text "BOW & TWIST:" at 11407.23,4537.64 h60
  text "X" at 12246.53,4537.64 h60
  text "ANSI IPC-6012 TYPE 3 CLASS 2" at 12433.48,4537.64 h60
  text "OTHER +/-" at 12433.46,4379.13 h60
  text "COPPER THICKNESS (FINISHED):" at 11332.46,4243.64 h60
  text "1.4MIL (1oz)" at 12212.46,4090.92 h60
  text "2MIL (1.4oz)" at 12979.46,4090.92 h60
  text "2.8MIL (2oz)" at 13706.46,4090.92 h60
  text "OUTER:" at 11689.46,4086.64 h60
  text "X" at 12084,4086 h60
  text "1.4MIL (1oz)" at 12212.46,3933.92 h60
  text "2.8MIL (2oz)" at 12979.46,3933.92 h60
  text "N/A" at 13706,3934.29 h60
  text "INNER SIGNAL:" at 11400.38,3929.64 h60
  text "X" at 12085.42,3929.64 h60
  text "DRILLING:" at 11332.46,3790.64 h60
  text "REFERENCE:" at 11407.23,3673.64 h60
  text "X" at 12055.46,3673.64 h60
  text "AS SHOWN" at 12242.46,3673.64 h60
  text "X" at 12956.46,3673.64 h60
  text "NC_DRILL FILES" at 13093.46,3673.64 h60
  text "PTH MIN COPPER THICKNESS:" at 11407.23,3515.64 h60
  text "X" at 12757.46,3515.64 h60
  text "1MIL" at 12894.46,3515.64 h60
  text "OTHER" at 13391.46,3515.64 h60
  text "BOARD FINISH:" at 11332.46,3356.64 h60
  text "SILKSCREEN:" at 11487.68,3238.64 h60
  text "X" at 12436.46,3238.64 h60
  text "TOP" at 12562.46,3238.64 h60
  text "X" at 12946.46,3238.64 h60
  text "BOTTOM" at 13073.46,3238.64 h60
  text "SILKSCREEN COLOR:" at 11487.68,3071.64 h60
  text "X" at 12435.42,3071.64 h60
  text "WHITE" at 12562.46,3071.64 h60
  text "OTHER" at 13073.46,3071.64 h60
  text "SOLDER RESIST COLOR:" at 11487.68,2901.64 h60
  text "X" at 12055.42,2742.44 h60
  text "GREEN" at 12182.46,2742.44 h60
  text "BLUE" at 12773.46,2742.44 h60
  text "OTHER" at 13311.46,2742.44 h60
  text "IMMERSION GOLD (ENIG)" at 12393.46,2553.92 h60
  text "ENEPIG" at 13731,2550.64 h60
  text "SURFACE FINISH:" at 11332.46,2549.64 h60
  text "X" at 12206.51,2549.64 h60
  text "IMM. TIN/SILVER OR EQUIV" at 11662,2392.64 h60
  text "OTHER" at 13093.46,2392.64 h60
  text "ARRAY/PANEL:" at 11332.46,2213.64 h60
  text "CUT AND TRIM PER MECH LAYER 1" at 12393.46,2209.35 h60
  text "X" at 12209,2062 h60
  text "N.C. ROUTE" at 12393.46,2057.64 h60
  text "V. SCORE" at 13259.46,2057.64 h60
  text "CERTIFICATION:" at 11332.46,1920.64 h60
  text "MATERIALS AND WORKMANSHIP FOR ALL PCBS" at 12057.46,1920.64 h60
  text "TO MEET OR EXCEED THE REQUIREMENTS OF:" at 12057.46,1822.64 h60
  text "X" at 11683.96,1686.13 h60
  text "ANSI IPC-A-600F CLASS ->" at 11822.96,1686.13 h60
  text "X" at 13462.02,1686.13 h60
  text "2" at 13580.96,1686.14 h60
  text "1" at 13265.96,1684.64 h60
  text "3" at 13934.96,1684.64 h60
  text "X" at 11686.02,1526.64 h60
  text "UL 94V-0" at 11822.96,1526.64 h60
  text "X" at 12498.02,1526.64 h60
  text "RoHS" at 12634.96,1526.64 h60
  text "OTHER" at 13279.36,1526.64 h60
  text "PER ORDER" at 13676.42,1526.64 h60
  text "ADDITIONAL REQUIREMENTS:" at 11332.46,1385.64 h60
  text "MICROSECTION:" at 11407.23,1270.64 h60
  text "YES" at 12312.96,1270.64 h60
  text "REQUIRED" at 13174.46,1114.49 h60
  text "BARE BOARD ELEC. TEST:" at 11407.23,1111.64 h60
  text "NONE" at 12712.96,1111.64 h60
  text "X" at 13047.46,1111.64 h60
  text "PER ORDER" at 13766.46,1111.64 h60
  text "MANUFACTURER'S UL:" at 11407.23,954.64 h60
  text "RAIL" at 12572.96,950.35 h60
  text "METAL" at 13064.77,950.35 h60
  text "X" at 13440,950 h60
  text "SILK" at 13576.46,950.35 h60
  text ".Layer_Name" at 577,-858.49 h60
M11 Gerber Information:
  lines w10: -292,-930.17 6308,-930.17 ; -292,-726.83 6310,-726.83 ; -292,-523.5 -292,-1133.5 3713,-1133.5 6310,-1133.5 6310,-523.5 -291.5,-523.5 -291.5,-1133.5 1284,-1133.5 ; 2173,-1133.5 2173,-523.5 ; 3440,-726.83 3440,-523.5 ; 4280,-726.83 4280,-523.5 ; 4902,-1140 4902,-937.17
  text "ALL ARTWORK VIEWED FROM TOP SIDE" at -228.5,-655.67 h60
  text "BOARD #:" at 2248,-655.67 h60
  text "TIDA-01465" at 2793.5,-655.67 h60
  text "REV:" at 3638,-655.67 h60
  text ".PCB_Rev" at 3929.5,-655.67 h60
  text "SVN REV:" at 4476,-655.67 h60
  text ".VersionControl_RevNumber" at 4982,-655.67 h60
  text "TIDA-01465" at 2801.44,-848.31 h60
  text "LAYER NAME =" at -228.5,-858.49 h60
  text "TID #:" at 2246.01,-858.24 h60
  text "PLOT NAME =" at -228.5,-1064.34 h60
  text ".plot_File_Name" at 577,-1064.34 h60
  text "GENERATED    :" at 2250,-1064.34 h60
  text ".Print_Date" at 3119.5,-1064.34 h60
  text ".Print_Time" at 3848.5,-1064.34 h60
  text "TEXAS INSTRUMENTS" at 5113,-1064.34 h60
M12 Stackup:
  lines w6: 11365,7632.25 14230,7632.25 ; 11365,7744.85 14230,7744.85 ; 11286,6907 ccw(c11322,6907) 11322,6871 14235,6871 ccw(c14235,6907) 14271,6907 14271,7902 ccw(c14235,7902) 14235,7938 11322,7938 ccw(c11322,7902) 11286,7902 11286,6907
  text "Layer Stack Up Detail for: SV601147B.PcbDoc" at 11346,7819.02 h58
  text "Layer" at 11365,7702.85 h26
  text "Gerber" at 12072.2,7702.85 h26
  text "Copper" at 12433.65,7702.85 h26
  text "Dielectric" at 12837.55,7702.85 h26
  text "Dielectric" at 13259.64,7702.85 h26
  text "Dielectric" at 13786.9,7702.85 h26
  text "Name" at 11365,7650.85 h26
  text "Document" at 12072.2,7650.85 h26
  text "Thickness" at 12433.65,7650.85 h26
  text "Height" at 12837.55,7650.85 h26
  text "Material" at 13259.64,7650.85 h26
  text "Type" at 13786.9,7650.85 h26
  text "Top Solder Mask" at 11365,7573.68 h36
  text "(.GTS)" at 12072.2,7573.68 h36
  text "0.4mil" at 12837.55,7573.68 h36
  text "Solder Resist" at 13259.64,7573.68 h36
  text "Top Layer" at 11365,7462.53 h36
  text "(.GTL)" at 12072.2,7462.53 h36
  text "1.4mil" at 12433.65,7462.53 h36
  text "12.6mil" at 12837.55,7406.96 h36
  text "FR-4" at 13259.64,7406.96 h36
  text "Core" at 13786.9,7406.96 h36
  text "MidLayer1" at 11365,7351.39 h36
  text "(.G1)" at 12072.2,7351.39 h36
  text "1.4mil" at 12433.65,7351.39 h36
  text "30.4mil" at 12837.55,7295.81 h36
  text "FR-4" at 13259.64,7295.81 h36
  text "PrePreg" at 13786.9,7295.81 h36
  text "MidLayer2" at 11365,7240.24 h36
  text "(.G2)" at 12072.2,7240.24 h36
  text "1.4mil" at 12433.65,7240.24 h36
  text "12.6mil" at 12837.55,7184.67 h36
  text "FR-4" at 13259.64,7184.67 h36
  text "Core" at 13786.9,7184.67 h36
  text "Bottom Layer" at 11365,7129.09 h36
  text "(.GBL)" at 12072.2,7129.09 h36
  text "1.4mil" at 12433.65,7129.09 h36
  text "Bottom Solder Mask" at 11365,7017.95 h36
  text "(.GBS)" at 12072.2,7017.95 h36
  text "0.4mil" at 12837.55,7017.95 h36
  text "Solder Resist" at 13259.64,7017.95 h36
  text ".Layer_Name" at 577,-858.49 h60
M13 Component Bodies Top:
  text ".Layer_Name" at 577,-858.49 h60
M14 Component Bodies Bottom:
  text ".Layer_Name" at 577,-858.49 h60
M15 Courtyards Top:
  text ".Layer_Name" at 577,-858.49 h60
M16 Courtyards Bottom:
  text ".Layer_Name" at 577,-858.49 h60
Drill Drawing:
  text ".Layer_Name" at 577,-858.49 h60

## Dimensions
0,0 to 2760,0 on M2 Board Dimensions
0,0 to -10,2010 on M2 Board Dimensions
